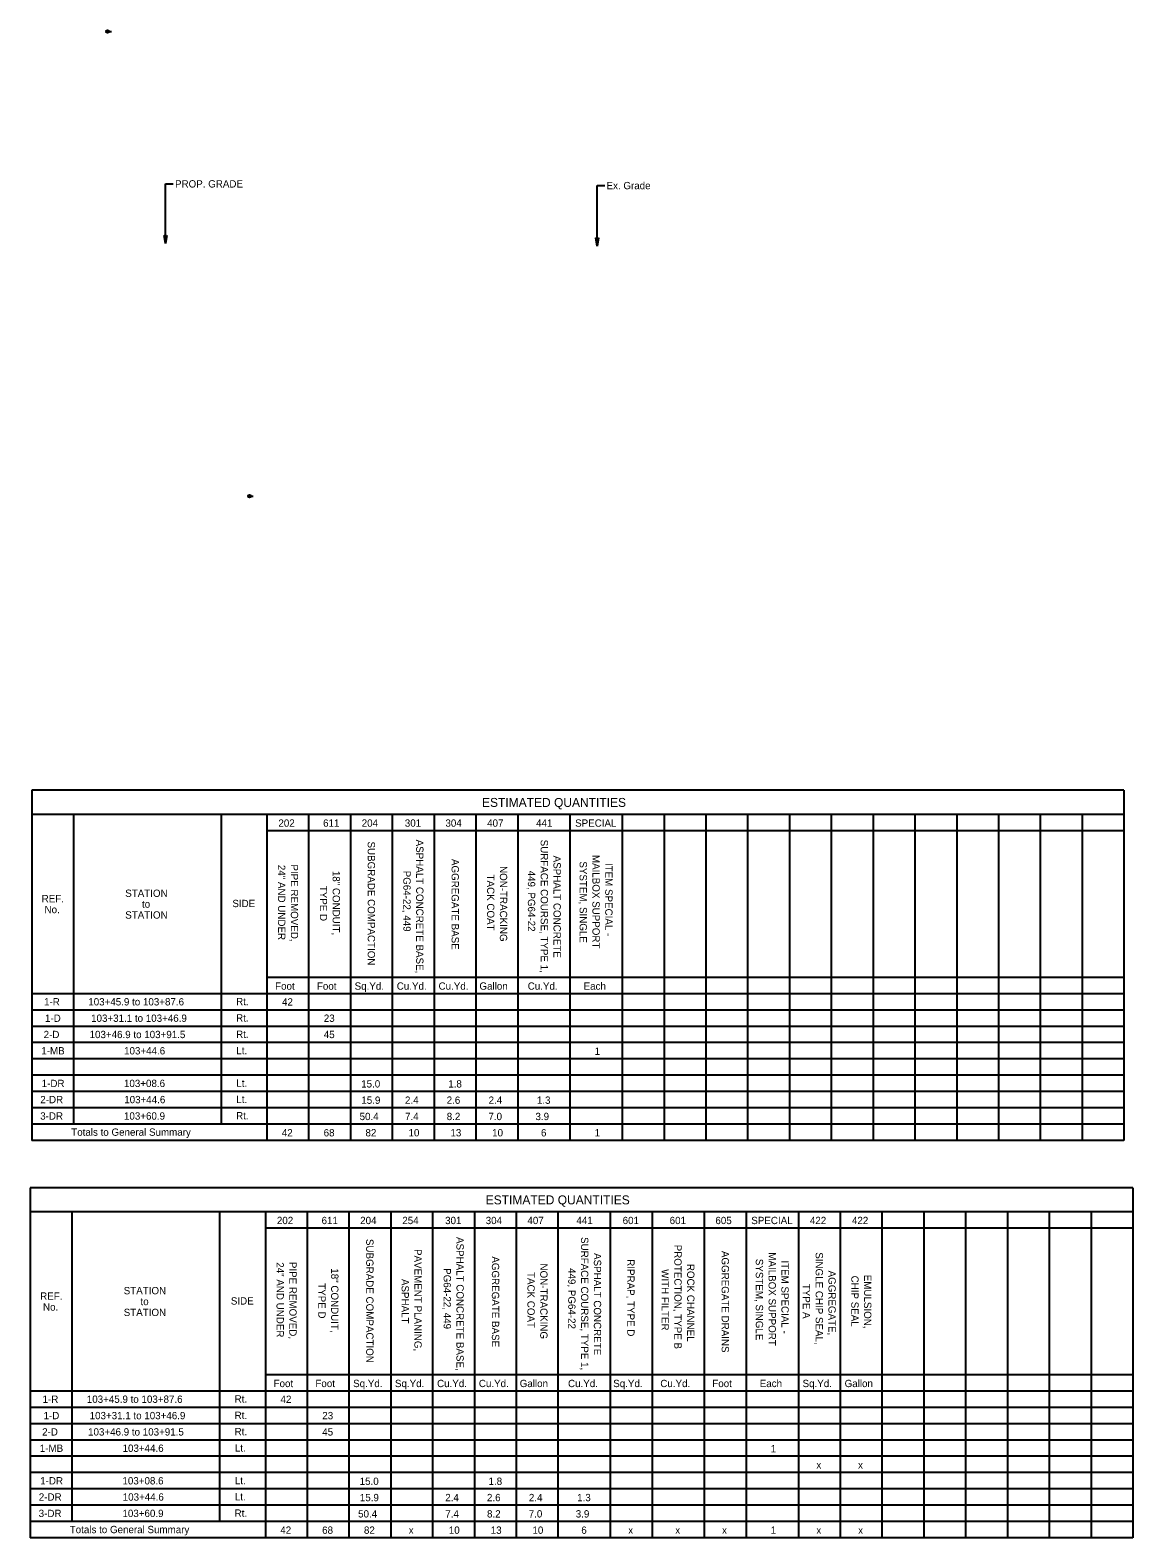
# Model space of a CAD drawing. Extents: x -44 to 74, y -34 to 24.
# Drawn here: x 12.02 to 33.12, y -34.46 to -5.6 of the extents above; entities that cross this region are included whole.
import ezdxf

# ---------------------------------------------------------------- set-up
doc = ezdxf.new("R2010")
doc.units = 0
for name, color, linetype in [('Default', 7, 'Continuous'), ('DR_X_Culvert', 7, 'Continuous'), ('GE_X_Alignment_100_Bearings', 7, 'Continuous'), ('GE_X_Alignment_100_Curve_Data', 7, 'Continuous'), ('PF_P_Text', 7, 'Continuous'), ('PF_X_Text', 7, 'Continuous')]:
    doc.layers.add(name, color=color, linetype=linetype)

msp = doc.modelspace()

# ---------------------------------------------------------------- linework, layer by layer
at = {"layer": 'Default'}
for p, q in [((13.48, -5.627), (13.532, -5.627)), ((13.506, -5.627), (13.582, -5.627)), ((16.196, -14.52), (16.248, -14.52)), ((16.222, -14.52), (16.294, -14.52))]:
    msp.add_line(p, q, dxfattribs=at)
for centre in [(13.506, -5.627), (16.222, -14.52)]:
    msp.add_circle(centre, 0.026, dxfattribs=at)
at = {"layer": 'GE_X_Alignment_100_Bearings'}
for p, q in [((12.053, -20.152), (12.053, -26.854)), ((32.953, -20.152), (12.053, -20.152)), ((32.953, -20.152), (32.953, -26.854)), ((32.953, -20.614), (12.053, -20.614)), ((12.853, -20.614), (12.853, -26.542)), ((15.678, -20.614), (15.678, -26.542)), ((16.553, -20.614), (16.553, -26.854)), ((17.353, -20.614), (17.353, -26.854)), ((18.153, -20.614), (18.153, -26.854)), ((18.953, -20.614), (18.953, -26.854)), ((19.753, -20.614), (19.753, -26.854)), ((20.553, -20.614), (20.553, -26.854)), ((21.353, -20.614), (21.353, -26.854)), ((22.353, -20.614), (22.353, -26.854)), ((23.353, -20.614), (23.353, -26.854)), ((24.153, -20.614), (24.153, -26.854)), ((24.953, -20.614), (24.953, -26.854)), ((25.753, -20.614), (25.753, -26.854)), ((26.553, -20.614), (26.553, -26.854)), ((27.353, -20.614), (27.353, -26.854)), ((28.153, -20.614), (28.153, -26.854)), ((28.953, -20.614), (28.953, -26.854)), ((29.753, -20.614), (29.753, -26.854)), ((30.553, -20.614), (30.553, -26.854)), ((31.353, -20.614), (31.353, -26.854)), ((32.153, -20.614), (32.153, -26.854)), ((32.953, -20.926), (16.553, -20.926)), ((32.953, -23.734), (16.553, -23.734)), ((32.953, -24.046), (12.053, -24.046)), ((32.953, -24.358), (12.053, -24.358)), ((32.953, -24.67), (12.053, -24.67)), ((32.953, -24.982), (12.053, -24.982)), ((32.953, -25.294), (12.053, -25.294)), ((32.953, -25.606), (12.053, -25.606)), ((32.953, -25.918), (12.053, -25.918)), ((32.953, -26.23), (12.053, -26.23)), ((32.953, -26.542), (12.053, -26.542)), ((32.953, -26.854), (12.053, -26.854)), ((12.024, -27.759), (12.024, -34.461)), ((33.124, -27.759), (12.024, -27.759)), ((33.124, -27.759), (33.124, -34.461)), ((33.124, -28.221), (12.024, -28.221)), ((12.824, -28.221), (12.824, -34.149)), ((15.649, -28.221), (15.649, -34.149)), ((16.524, -28.221), (16.524, -34.461)), ((17.324, -28.221), (17.324, -34.461)), ((18.124, -28.221), (18.124, -34.461)), ((18.924, -28.221), (18.924, -34.461)), ((19.724, -28.221), (19.724, -34.461)), ((20.524, -28.221), (20.524, -34.461)), ((21.324, -28.221), (21.324, -34.461)), ((22.124, -28.221), (22.124, -34.461)), ((23.124, -28.221), (23.124, -34.461)), ((23.924, -28.221), (23.924, -34.461)), ((24.924, -28.221), (24.924, -34.461)), ((25.724, -28.221), (25.724, -34.461)), ((26.724, -28.221), (26.724, -34.461)), ((27.524, -28.221), (27.524, -34.461)), ((28.324, -28.221), (28.324, -34.461)), ((29.124, -28.221), (29.124, -34.461)), ((29.924, -28.221), (29.924, -34.461)), ((30.724, -28.221), (30.724, -34.461)), ((31.524, -28.221), (31.524, -34.461)), ((32.324, -28.221), (32.324, -34.461)), ((33.124, -28.533), (16.524, -28.533)), ((33.124, -31.341), (16.524, -31.341)), ((33.124, -31.653), (12.024, -31.653)), ((33.124, -31.965), (12.024, -31.965)), ((33.124, -32.277), (12.024, -32.277)), ((33.124, -32.589), (12.024, -32.589)), ((33.124, -32.901), (12.024, -32.901)), ((33.124, -33.213), (12.024, -33.213)), ((33.124, -33.525), (12.024, -33.525)), ((33.124, -33.837), (12.024, -33.837)), ((33.124, -34.149), (12.024, -34.149)), ((33.124, -34.461), (12.024, -34.461))]:
    msp.add_line(p, q, dxfattribs=at)
at = {"layer": 'PF_P_Text'}
for p, q in [((14.611, -9.686), (14.611, -8.54)), ((22.871, -9.733), (22.871, -8.576)), ((14.611, -9.686), (14.585, -9.531)), ((14.585, -9.531), (14.585, -9.532)), ((14.636, -9.532), (14.611, -9.686)), ((14.636, -9.532), (14.636, -9.532)), ((22.871, -9.733), (22.845, -9.579)), ((22.845, -9.579), (22.845, -9.579)), ((22.897, -9.579), (22.871, -9.733)), ((22.897, -9.579), (22.897, -9.579))]:
    msp.add_line(p, q, dxfattribs=at)
for centre in [(14.611, -9.493), (22.871, -9.54)]:
    msp.add_arc(centre, 0.0469, 236.178, 302.8588, dxfattribs=at)
at = {"layer": 'PF_X_Text'}
for p, q in [((14.611, -8.54), (14.761, -8.54)), ((22.871, -8.576), (23.021, -8.576))]:
    msp.add_line(p, q, dxfattribs=at)

# ---------------------------------------------------------------- texts
at = {"layer": 'Default'}
for s, p in [('Plan 1', (13.5, -5.637)), ('4', (13.505, -5.62)), ('CLX_148 - Profile 1-1', (13.539, -5.62)), ('1:20', (13.539, -5.637)), ('Plan 1', (16.216, -14.53)), ('2', (16.22, -14.513)), ('CLX_148 - Profile 1', (16.254, -14.513)), ('1:20', (16.254, -14.53))]:
    msp.add_text(s, height=0.00328, dxfattribs=at).set_placement(p)
at = {"layer": 'DR_X_Culvert'}
msp.add_text('PROP. GRADE', height=0.14, dxfattribs=at).set_placement((14.796, -8.613))
at = {"layer": 'GE_X_Alignment_100_Bearings'}
for p in [(20.67, -20.47), (20.741, -28.078)]:
    msp.add_text('ESTIMATED QUANTITIES', height=0.17175, rotation=360, dxfattribs=at).set_placement(p)
at = {"layer": 'GE_X_Alignment_100_Curve_Data'}
for s, rotation, p in [('202', 360, (16.774, -20.849)), ('611', 360, (17.629, -20.849)), ('204', 360, (18.368, -20.849)), ('301', 360, (19.193, -20.849)), ('304', 360, (19.97, -20.849)), ('407', 360, (20.768, -20.849)), ('441', 360, (21.705, -20.849)), ('SPECIAL', 360, (22.452, -20.849)), ('SUBGRADE COMPACTION', 270, (18.483, -21.132)), ('ASPHALT CONCRETE BASE,', 270, (19.41, -21.096)), ('SURFACE COURSE, TYPE 1,', 270, (21.793, -21.097)), ('24" AND UNDER', 270, (16.767, -21.579)), ('PIPE REMOVED,', 270, (17.012, -21.571)), ('AGGREGATE BASE', 270, (20.088, -21.466)), ('NON-TRACKING', 270, (21.012, -21.602)), ('ASPHALT CONCRETE', 270, (22.038, -21.403)), ('SYSTEM, SINGLE', 270, (22.538, -21.512)), ('MAILBOX SUPPORT', 270, (22.783, -21.389)), ('ITEM SPECIAL -', 270, (23.028, -21.542)), ('18" CONDUIT,', 270, (17.812, -21.694)), ('PG64-22, 449', 270, (19.165, -21.691)), ('TACK COAT', 270, (20.767, -21.765)), ('449, PG64-22', 270, (21.548, -21.69)), ('REF.', 360, (12.244, -22.296)), ('STATION', 360, (13.843, -22.192)), ('TYPE D', 270, (17.567, -21.979)), ('No.', 360, (12.299, -22.504)), ('STATION', 360, (13.843, -22.608)), ('to', 360, (14.164, -22.4)), ('SIDE', 360, (15.893, -22.388)), ('Foot', 360, (16.711, -23.969)), ('Foot', 360, (17.511, -23.969)), ('Sq.Yd.', 360, (18.233, -23.969)), ('Cu.Yd.', 360, (19.039, -23.969)), ('Cu.Yd.', 360, (19.839, -23.969)), ('Gallon', 360, (20.621, -23.969)), ('Cu.Yd.', 360, (21.545, -23.969)), ('Each', 360, (22.614, -23.969)), ('1-R', 360, (12.29, -24.27)), ('103+45.9 to 103+87.6', 360, (13.136, -24.27)), ('Rt.', 360, (15.965, -24.265)), ('42', 360, (16.843, -24.272)), ('1-D', 360, (12.308, -24.584)), ('103+31.1 to 103+46.9', 360, (13.19, -24.584)), ('Rt.', 360, (15.965, -24.579)), ('23', 360, (17.643, -24.584)), ('2-D', 360, (12.282, -24.896)), ('103+46.9 to 103+91.5', 360, (13.161, -24.896)), ('Rt.', 360, (15.965, -24.891)), ('45', 360, (17.642, -24.896)), ('1-MB', 360, (12.237, -25.208)), ('103+44.6', 360, (13.821, -25.208)), ('Lt.', 360, (15.969, -25.203)), ('1', 360, (22.824, -25.217)), ('1-DR', 360, (12.244, -25.832)), ('103+08.6', 360, (13.819, -25.832)), ('Lt.', 360, (15.969, -25.827)), ('15.0', 360, (18.358, -25.841)), ('1.8', 360, (20.024, -25.841)), ('2-DR', 360, (12.218, -26.142)), ('103+44.6', 360, (13.824, -26.142)), ('Lt.', 360, (15.969, -26.137)), ('15.9', 360, (18.361, -26.153)), ('2.4', 360, (19.196, -26.153)), ('2.6', 360, (19.994, -26.153)), ('2.4', 360, (20.796, -26.153)), ('1.3', 360, (21.72, -26.153)), ('3-DR', 360, (12.216, -26.456)), ('103+60.9', 360, (13.819, -26.456)), ('Rt.', 360, (15.965, -26.451)), ('50.4', 360, (18.328, -26.465)), ('7.4', 360, (19.197, -26.465)), ('8.2', 360, (19.995, -26.465)), ('7.0', 360, (20.793, -26.465)), ('3.9', 360, (21.693, -26.465)), ('Totals to General Summary', 360, (12.81, -26.765)), ('42', 360, (16.839, -26.777)), ('68', 360, (17.64, -26.777)), ('82', 360, (18.44, -26.777)), ('10', 360, (19.264, -26.777)), ('13', 360, (20.066, -26.777)), ('10', 360, (20.864, -26.777)), ('6', 360, (21.799, -26.777)), ('1', 360, (22.824, -26.777)), ('202', 360, (16.745, -28.456)), ('611', 360, (17.6, -28.456)), ('204', 360, (18.339, -28.456)), ('254', 360, (19.145, -28.456)), ('301', 360, (19.964, -28.456)), ('304', 360, (20.741, -28.456)), ('407', 360, (21.539, -28.456)), ('441', 360, (22.476, -28.456)), ('601', 360, (23.361, -28.456)), ('601', 360, (24.261, -28.456)), ('605', 360, (25.136, -28.456)), ('SPECIAL', 360, (25.823, -28.456)), ('422', 360, (26.944, -28.456)), ('422', 360, (27.749, -28.456)), ('SUBGRADE COMPACTION', 270, (18.454, -28.74)), ('ASPHALT CONCRETE BASE,', 270, (20.181, -28.703)), ('SURFACE COURSE, TYPE 1,', 270, (22.565, -28.704)), ('PAVEMENT PLANING,', 270, (19.376, -28.933)), ('AGGREGATE BASE', 270, (20.859, -29.073)), ('ASPHALT CONCRETE', 270, (22.81, -29.01)), ('RIPRAP, TYPE D', 270, (23.45, -29.128)), ('PROTECTION, TYPE B', 270, (24.35, -28.85)), ('AGGREGATE DRAINS', 270, (25.256, -28.969)), ('SYSTEM, SINGLE', 270, (25.909, -29.12)), ('MAILBOX SUPPORT', 270, (26.154, -28.996)), ('SINGLE CHIP SEAL,', 270, (27.054, -28.995)), ('24" AND UNDER', 270, (16.738, -29.186)), ('PIPE REMOVED,', 270, (16.983, -29.179)), ('18" CONDUIT,', 270, (17.783, -29.302)), ('PG64-22, 449', 270, (19.936, -29.299)), ('TACK COAT', 270, (21.539, -29.373)), ('NON-TRACKING', 270, (21.784, -29.21)), ('449, PG64-22', 270, (22.32, -29.297)), ('WITH FILTER', 270, (24.105, -29.318)), ('ROCK CHANNEL', 270, (24.595, -29.217)), ('ITEM SPECIAL -', 270, (26.399, -29.15)), ('AGGREGATE,', 270, (27.299, -29.346)), ('STATION', 360, (13.814, -29.799)), ('TYPE D', 270, (17.538, -29.587)), ('ASPHALT', 270, (19.131, -29.506)), ('TYPE A', 270, (26.809, -29.598)), ('CHIP SEAL', 270, (27.736, -29.442)), ('EMULSION,', 270, (27.981, -29.425)), ('REF.', 360, (12.215, -29.903)), ('No.', 360, (12.27, -30.112)), ('to', 360, (14.135, -30.007)), ('SIDE', 360, (15.864, -29.996)), ('STATION', 360, (13.814, -30.216)), ('Foot', 360, (16.682, -31.576)), ('Foot', 360, (17.482, -31.576)), ('Sq.Yd.', 360, (18.204, -31.576)), ('Sq.Yd.', 360, (19.004, -31.576)), ('Cu.Yd.', 360, (19.81, -31.576)), ('Cu.Yd.', 360, (20.61, -31.576)), ('Gallon', 360, (21.392, -31.576)), ('Cu.Yd.', 360, (22.316, -31.576)), ('Sq.Yd.', 360, (23.181, -31.576)), ('Cu.Yd.', 360, (24.082, -31.576)), ('Foot', 360, (25.077, -31.576)), ('Each', 360, (25.985, -31.576)), ('Sq.Yd.', 360, (26.804, -31.576)), ('Gallon', 360, (27.609, -31.576)), ('1-R', 360, (12.261, -31.877)), ('103+45.9 to 103+87.6', 360, (13.108, -31.877)), ('Rt.', 360, (15.936, -31.872)), ('42', 360, (16.814, -31.879)), ('1-D', 360, (12.28, -32.191)), ('103+31.1 to 103+46.9', 360, (13.162, -32.191)), ('Rt.', 360, (15.936, -32.186)), ('23', 360, (17.614, -32.191)), ('2-D', 360, (12.253, -32.503)), ('103+46.9 to 103+91.5', 360, (13.132, -32.503)), ('Rt.', 360, (15.936, -32.498)), ('45', 360, (17.613, -32.503)), ('1-MB', 360, (12.208, -32.815)), ('103+44.6', 360, (13.792, -32.815)), ('Lt.', 360, (15.94, -32.81)), ('1', 360, (26.195, -32.824)), ('x', 360, (27.068, -33.136)), ('x', 360, (27.866, -33.136)), ('1-DR', 360, (12.216, -33.439)), ('103+08.6', 360, (13.79, -33.439)), ('Lt.', 360, (15.94, -33.434)), ('15.0', 360, (18.329, -33.448)), ('1.8', 360, (20.795, -33.448)), ('2-DR', 360, (12.189, -33.749)), ('103+44.6', 360, (13.795, -33.749)), ('Lt.', 360, (15.94, -33.744)), ('15.9', 360, (18.332, -33.76)), ('2.4', 360, (19.967, -33.76)), ('2.6', 360, (20.765, -33.76)), ('2.4', 360, (21.567, -33.76)), ('1.3', 360, (22.491, -33.76)), ('3-DR', 360, (12.187, -34.063)), ('103+60.9', 360, (13.79, -34.063)), ('Rt.', 360, (15.936, -34.058)), ('50.4', 360, (18.299, -34.072)), ('7.4', 360, (19.968, -34.072)), ('8.2', 360, (20.766, -34.072)), ('7.0', 360, (21.564, -34.072)), ('3.9', 360, (22.464, -34.072)), ('Totals to General Summary', 360, (12.781, -34.372)), ('42', 360, (16.81, -34.384)), ('68', 360, (17.611, -34.384)), ('82', 360, (18.411, -34.384)), ('x', 360, (19.268, -34.384)), ('10', 360, (20.035, -34.384)), ('13', 360, (20.837, -34.384)), ('10', 360, (21.635, -34.384)), ('6', 360, (22.57, -34.384)), ('x', 360, (23.468, -34.384)), ('x', 360, (24.368, -34.384)), ('x', 360, (25.263, -34.384)), ('1', 360, (26.195, -34.384)), ('x', 360, (27.068, -34.384)), ('x', 360, (27.868, -34.384))]:
    msp.add_text(s, height=0.14, rotation=rotation, dxfattribs=at).set_placement(p)
at = {"layer": 'PF_X_Text'}
msp.add_text('Ex. Grade', height=0.14, dxfattribs=at).set_placement((23.053, -8.646))

doc.saveas('drawing.dxf')
